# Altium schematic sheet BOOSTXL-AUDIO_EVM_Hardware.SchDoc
size 431 x 279 mm; Date: Not shown in title block; ApprovedBy: Not shown in title block; CheckedBy: Not shown in title block; Author: Not shown in title block; CompanyName: Not shown in title block; Engineer: Not shown in title block; Organization: Not shown in title block; Address1: Not shown in title block; Address2: Not shown in title block; Address3: Not shown in title block; Address4: Not shown in title block; DocumentNumber: 1; Revision: Use project parameter SCH_Rev; SheetNumber: 2; SheetTotal: 2; PageSetup: Record=PageOptions¦CenterHorizontal=True¦CenterVertical=True¦PrintScale=1.00¦XCorrection=1.00¦YCorrection=1.00¦PrintKind=0¦BorderSize=5000000¦LeftOffset=0¦BottomOffset=0¦Orientation=2¦PaperLength=1000¦PaperWidth=1000¦Scale=100¦PaperSource=15¦PrintQuality=600¦MediaType=1¦DitherType=10¦PaperKind=Letter¦PrintScaleMode=1
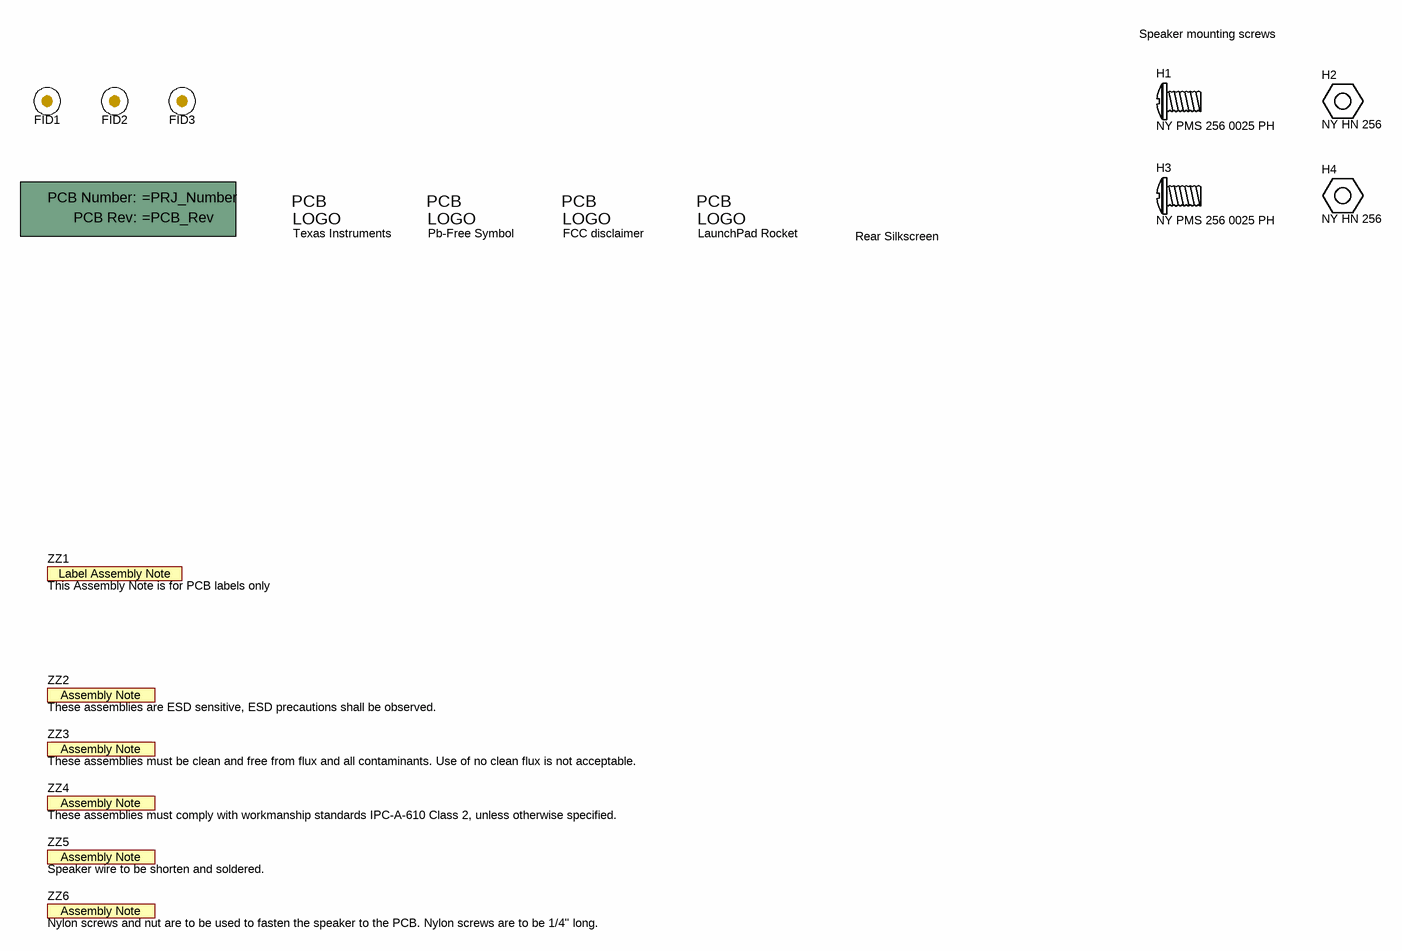
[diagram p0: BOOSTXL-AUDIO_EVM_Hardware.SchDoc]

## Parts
!PCB1  Printed Circuit Board  (value not drawn)  (mechanical)
FID1  Fiducial  [Fiducial10-20]  (value not drawn)
FID2  Fiducial  [Fiducial10-20]  (value not drawn)
FID3  Fiducial  [Fiducial10-20]  (value not drawn)
H1  NY PMS 256 0025 PH  (mechanical)
H2  NY HN 256  (mechanical)
H3  NY PMS 256 0025 PH  (mechanical)
H4  NY HN 256  (mechanical)
Logo1  Texas Instruments  [TI_Stacked_Overlay_Small]  (no BOM)
Logo2  Pb-Free Symbol  [Pb-Free_Overlay_Small]  (no BOM)
Logo3  FCC disclaimer  [FCC_disclaimer]  (no BOM)
Logo4  LaunchPad Rocket  [LaunchPadRocket_Small]  (no BOM)
S?  (no value)  [BOOSTXL-AUDIO_RearSilk]
ZZ1  This Assembly Note is for PCB labels only  [AssemblyNoteLabel]  (no BOM)
ZZ2  These assemblies are ESD sensitive, ESD precautions shall be observed.  [AssemblyNote]  (no BOM)
ZZ3  These assemblies must be clean and free from flux and all contaminants. Use of no clean flux is not acceptable.  [AssemblyNote]  (no BOM)
ZZ4  These assemblies must comply with workmanship standards IPC-A-610 Class 2, unless otherwise specified.  [AssemblyNote]  (no BOM)
ZZ5  Speaker wire to be shorten and soldered.  [AssemblyNote]  (no BOM)
ZZ6  Nylon screws and nut are to be used to fasten the speaker to the PCB. Nylon screws are to be 1/4" long.  [AssemblyNote]  (no BOM)

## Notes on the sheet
- Speaker mounting screws

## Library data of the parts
!PCB1 = PCB: Manufacturer: Any; SymbolCreator: a0412235
FID1-FID3 = Fiducial: Fiducial mark.  There is nothing to buy or mount.; SymbolCreator: codlsc
H1 H3 = NY PMS 256 0025 PH: Nylon Screw, Panhead, Phillips, 2-56; Manufacturer: B&F Fastener Supply; SymbolCreator: a0412235
H2 H4 = NY HN 256: Nylon Nut, 2-56, 3/16"; Manufacturer: B&F Fastener Supply; SymbolCreator: a0412235
Logo1 = TI_Logo: Texas Instrument Corporate Signature; SymbolCreator: codlsc
Logo2 = Pb-Free: SymbolCreator: a0412235
Logo3 = FCC_disclaimer: SymbolCreator: codlsc
Logo4 = LaunchPad_Rocket: LaunchPad Rocket logo; SymbolCreator: a0412235
S? = Rear Silkscreen: SymbolCreator: a0273630; U/M: EA, IN, or GM
ZZ1 = AssemblyNoteLabel: SymbolCreator: a0412235
ZZ2-ZZ6 = AssemblyNote: SymbolCreator: codlsc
